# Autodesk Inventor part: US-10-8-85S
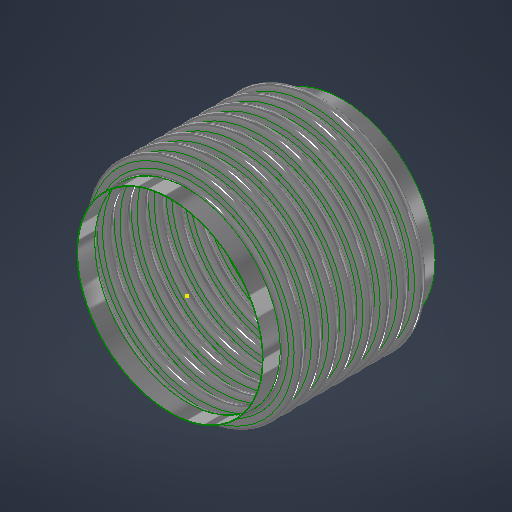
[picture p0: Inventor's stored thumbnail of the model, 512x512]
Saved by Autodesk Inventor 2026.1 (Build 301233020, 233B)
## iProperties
Category: 20 GA (0.036 THICK)
RuleStatus: InUse
Created: 2026-07
Part Number: US-10-8-85S
Project: =STOCK BELLOWS: <Stock Number><SFILL>
Material: ASTM A240-304
Description: =STOCK BELLOWS: <Stock Number>, <SID_> I.D., <SOD_> O.D., <SPLY_> PLY, <Category>, <SNET_CONS> CONS.<PITCH_><STANGENT_> TANGENT<SFILL>
Document SubType Name: Sheet Metal
Designer: LC
Stock Number: U.S-10-8-85S
Surface Area: 659.127 cm^2
Volume: 56.61 cm^3
Sheet Metal Rule: Default
Appearance: STAINLESS STEEL
NET_TUBE: 3.428
COUNTER: 1.500
PBAR: 1.214
PSET: 5.356
PLY: 2
CONS: 2
THK: 0.036
ID: 4.500
OD: 5.500
CONS_: 2
TANGENT: 0.500
PITCH: 0.375
BELLOWS_UPSET: 0.000
NET_CONS: 2
S_CONS: 0
Description_Units: 0
ID_M: 114.30 mm
OD_M: 139.70 mm
THK_M: 0.91 mm
ID_U: 4.500 in
OD_U: 5.500 in
THK_U: 0.036 in
TANGENT2: 0.500
d79: 1.000
d82: 1.000
d83: 26.000
d84: 24.000
d80: 2.571
d81: 10
SID: 2.375
SCONS_: 8
SPITCH: 0.250
SBELLOWS_UPSET: 0.000
SNET_CONS: 8
SS_CONS: 0
SCONS: 8
d174: 8
d177: 0.018
d178: 2.375
d179: 3.000
d180: 0.375
d181: 1.000
d182: 0.000
d190: 8
d191: 1
d192: 1
d193: 8
d194: 0
PART_NUMBER: U.S-10-8-85S
PRESSURE: 85
SIZE: 10.00
STANGENT_: 1.000
d214: 8
d217: 0.030
d218: 6.625
d219: 8.125
d220: 0.500
d221: 1.000
d222: 0.000
d230: 8
d231: 1
d232: 1
d233: 8
d234: 0
STANGENT: 4.000
SPLY_: 1
STHK_: 0.036
SID_: 10.750
SOD_: 12.500
SPITCH_: 1.000
STANGENT__: 1.000
SBELLOWS_UPSET_: 0.000
SDIFF_TAN: 1.000
TAN_TO_TAN: 0.750 in
d252: 2
d275: 2
d287: 0.050
d289: 0.500
d290: 0.000
d263: 2
d265: 1
d268: 2
d269: 0
d286: 2
d288: 1
d291: 2
d292: 0
SOD_NECK: 10 13/16
CFILL: .
SFILL: .
PITCH_: =, <SPITCH_> PITCH,
SREROLL: 0.750
MATTABLE: 20 GA (0.036 THICK)
MESH: ,
CSECT: 2
Author: LC
Keywords: 20 GA (0.036 THICK)
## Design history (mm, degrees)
sketch "Sketch2"
  geometry: L1 (0, -183.595)-(0, 600.956) reference; L2 (58.979, 0)-(57.15, 0); L3 (60.446, -1.467)-(66.554, -1.467); L4 (60.446, -3.296)-(66.554, -3.296); L5 (66.554, -8.058)-(60.446, -8.058); L6 (66.554, -6.229)-(60.446, -6.229); L7 (58.979, -9.525)-(57.15, -9.525); L8 (60.446, 0)-(60.446, -9.525); L9 (66.554, -4.762)-(69.85, -4.763); L10 (57.15, 0)-(57.15, -9.525); L11 (20.376, 102.841)-(20.376, 101.926); L12 (58.262, 488.877)-(58.262, 349.177); L13 (58.262, 479.352)-(58.262, 339.652); L14 (93.133, -58.817)-(93.133, -71.517); L15 (118.746, -66.401)-(118.746, -66.401); L16 (66.554, -6.229)-(66.554, -8.058); L17 (60.446, -6.229)-(60.446, -8.058); L18 (60.446, -7.144)-(66.554, -7.144); L19 (69.85, 0)-(69.85, -9.525); L20 (-66.554, -6.229)-(-66.554, -8.058); L21 (-66.554, -1.467)-(-60.446, -1.467); L22 (-66.554, -3.296)-(-60.446, -3.296); L23 (-60.446, -6.229)-(-66.554, -6.229); L24 (-66.554, -7.144)-(-60.446, -7.144); L25 (-60.446, -8.058)-(-66.554, -8.058); L26 (-60.446, -6.229)-(-60.446, -8.058); L27 (-57.15, -2.522)-(-57.15, -12.047); L28 (-60.446, -4.763)-(-57.15, -4.763); L29 (-66.554, 3.828)-(-66.554, -9.525); L30 (-68.021, 0)-(-69.85, 0); L31 (-69.85, 0)-(-69.85, -9.525); L32 (-68.021, -9.525)-(-69.85, -9.525); A1 r 1.467 centre (60.446, 0) between (58.979, 0) and (60.446, -1.467); A2 r 3.296 centre (60.446, 0) between (57.15, 0) and (60.446, -3.296); A3 r 3.296 centre (66.554, -4.762) between (66.554, -8.058) and (66.554, -1.467); A4 r 1.467 centre (66.554, -4.762) between (66.554, -6.229) and (66.554, -3.296); A5 r 1.467 centre (60.446, -9.525) between (60.446, -8.058) and (58.979, -9.525); A6 r 3.296 centre (60.446, -9.525) between (60.446, -6.229) and (57.15, -9.525); A7 r 2.381 centre (66.554, -4.762) between (66.554, -7.144) and (68.936, -4.762); A8 r 2.381 centre (60.446, -9.525) between (60.446, -7.144) and (58.064, -9.525); A9 r 1.467 centre (-66.554, -9.525) between (-66.554, -8.058) and (-68.021, -9.525); A10 r 1.467 centre (-60.446, -4.763) between (-60.446, -6.229) and (-60.446, -3.296); A11 r 2.381 centre (-60.446, -4.763) between (-60.446, -7.144) and (-58.064, -4.763); A12 r 3.296 centre (-60.446, -4.763) between (-60.446, -8.058) and (-60.446, -1.467); A13 r 2.381 centre (-66.554, -9.525) between (-66.554, -7.144) and (-68.936, -9.525); A14 r 3.296 centre (-66.554, -9.525) between (-66.554, -6.229) and (-69.85, -9.525); A15 r 1.467 centre (-66.554, 0) between (-68.021, 0) and (-66.554, -1.467); A16 r 3.296 centre (-66.554, 0) between (-69.85, 0) and (-66.554, -3.296); 10 further points
  constraints: 62 end point, 38 point on circle, 20 tangent, 16 centre point, 12 parallel, 9 midpoint, 7 vertical, 6 coincident, 6 concentric, 6 point on line, 4 equal radius, 4 perpendicular, 3 horizontal, 1 collinear, 1 horizontal alignment, 10 other
  dimensions: "THK" = 0.9144 distance of L11.start L11.end; "ID" = 114.3 distance of L11.end point (20.376, -12.374); "OD" = 139.7 distance of L12.start L12.end; "PITCH" = 9.525 distance of L12.start L13.start; "TANGENT" = 12.7 distance of L14.start L14.end; "BELLOWS_UPSET" = 0 distance of L15.start L15.end; "d43" = 114.3 diameter of L10 L1 (= ID); "d44" = 139.7 diameter of L9.end L1 (= OD); "d45" = 1.8288 distance between parallel lines of L5 L6 (computed from THK, PLY); "d46" = 3.29565 radius of A3 (computed from PITCH, THK, PLY); "UPSET_PITCH" = 9.525 distance of L2.end L7.end (derived); "SIDEWALL_ANGLE" = 0 deg angle of L3 L9 (derived); "CON_GAP" = 2.9337 distance of point (60.446, -6.229) point (60.446, -3.296) (derived); "TAN1" = 3.74046 dimension on A8 (derived); "TAN2" = 3.74046 dimension on A7 (derived); "LEG1" = 6.1087 distance of L18.start L18.end (derived); "d278" = 1.8288 distance between parallel lines of L25 L23 (derived); "d279" = 3.29565 radius of A12 (derived); "d280" = 9.525 distance of L30.end L31.end (derived); "d281" = 360 deg dimension on L21 L28 (derived); "d282" = 2.9337 distance of point (-66.554, -6.229) point (-66.554, -3.296) (derived); "d283" = 3.74046 dimension on A13 (derived); "d284" = 3.74046 dimension on A11 (derived); "d285" = 6.1087 distance of L24.start L24.end (derived); "d293" = 114.3 diameter of L27 L1 (derived); "d294" = 139.7 diameter of L31 L1 (derived)
  node "Sketch Rectangular Pattern1" dims "d31" = 25.4, "ID" = 114.3
  node "Sketch Rectangular Pattern2" dims "d39" = 25.4, "PITCH" = 9.525
revolve "CONS" stored, may be unused: angle "d48" = 90 deg
node "BELLOW MIDPLANE"
pattern_linear "Rectangular Pattern2" dims "d52" = 9.525 (= UPSET_PITCH)
sketch "Sketch5"
  geometry: C1 r 58.979 at (0, 0) reference; C2 r 57.15 at (0, 0) reference
extrude "TANGENT" new body sketch "Sketch5" distance "d53" = 12.7 (= TANGENT); taper "d54" = 0 deg
revolve "SAMETAN" stored, may be unused: angle "d65" = 90 deg
revolve "DIFFTAN" stored, may be unused: angle "d70" = 90 deg
sketch "Sketch9"
  geometry: L1 (58.391, 0)-(-58.391, 0) reference; L2 (0, -17.78)-(0, 17.78) reference; L3 (41.708, 0)-(-41.708, 0); L4 (41.708, -11.906)-(41.708, 11.906); L5 (29.008, -11.906)-(29.008, 11.906); L6 (15.418, 11.906)-(15.418, -11.906); L7 (-29.008, -11.906)-(-29.008, 11.906); L8 (-41.708, -11.906)-(-41.708, 11.906); L9 (40.914, -11.906)-(40.914, 11.906); L10 (41.708, -11.906)-(40.914, -11.906); L11 (41.708, 11.906)-(40.914, 11.906); L12 (15.815, 11.906)-(15.022, 11.906); L13 (15.022, 11.906)-(15.022, -11.906); L14 (15.022, -11.906)-(15.815, -11.906); L15 (15.815, -11.906)-(15.815, 11.906); L16 (-15.815, 11.906)-(-15.815, -11.906); L17 (-15.418, 11.906)-(-15.418, -11.906); L18 (-15.815, -11.906)-(-15.022, -11.906); L19 (-15.022, -11.906)-(-15.022, 11.906); L20 (-15.022, 11.906)-(-15.815, 11.906); L21 (-41.708, -11.906)-(-40.914, -11.906); L22 (-40.914, -11.906)-(-40.914, 11.906); L23 (-40.914, 11.906)-(-41.708, 11.906); L24 (-41.708, 11.906)-(-41.708, -11.906); L25 (41.708, -0.397)-(-41.708, -0.397); L26 (-41.708, -0.397)-(-41.708, 0.397); L27 (-41.708, 0.397)-(41.708, 0.397); L28 (41.708, 0.397)-(41.708, -0.397); L29 (-41.708, 11.906)-(41.708, 11.906); L30 (41.708, 11.906)-(41.708, 12.7); L31 (41.708, 12.7)-(-41.708, 12.7); L32 (-41.708, 12.7)-(-41.708, 11.906); L33 (41.708, -11.906)-(-41.708, -11.906); L34 (-41.708, -11.906)-(-41.708, -12.7); L35 (-41.708, -12.7)-(41.708, -12.7); L36 (41.708, -12.7)-(41.708, -11.906); 30 further points
  constraints: 68 end point, 13 midpoint, 13 parallel, 8 horizontal, 7 perpendicular, 6 equal length, 3 point on line, 2 vertical, 14 other
  dimensions: "d115" = 23.8125 distance of L4.start L4.end (derived); "d116" = 12.7 distance between parallel lines of L4 L5 (derived); "d117" = 13.58962 distance between parallel lines of L5 L6 (derived); "d125" = 44.42645 distance between parallel lines of L7 L6 (derived); "d127" = 12.7 distance between parallel lines of L8 L7 (derived); "d128" = 26.28962 distance between parallel lines of L6 L4 (derived); "d130" = 83.41607 distance between parallel lines of L8 L4 (derived); "RULER_THK" = 0.79375 distance between parallel lines of L4 L9; "d135" = 0.79375 distance of L13.end L14.end (derived); "d138" = 30.83684 distance of L13.end L16.end (derived); "d143" = 0.79375 distance of L22.end L8.end (derived); "d144" = 0.79375 distance between parallel lines of L27 L25 (derived)
extrude "RULER" join sketch "Sketch9" distance "d149" = 0.79375 (derived); taper "d150" = 0 deg
extrude "BARS" join sketch "Sketch9" distance "d151" = 0.79375 (derived); taper "d152" = 0 deg
pattern_linear "Rectangular Pattern4" dims "d155" = 30.83684 (derived)
sketch "Sketch13"
  geometry: L1 (93.149, -52.467)-(93.149, -77.867); L2 (137.439, 0)-(136.525, 0); L3 (137.439, -25.4)-(136.525, -25.4); L4 (151.943, -19.507)-(143.332, -19.507); L5 (151.943, -18.593)-(143.332, -18.593); L6 (151.943, -12.7)-(158.75, -12.7); L7 (143.332, -5.893)-(151.943, -5.893); L8 (143.332, 0)-(143.332, -25.4); L9 (136.525, 0)-(136.525, -25.4); L10 (58.254, -287.939)-(58.254, -605.439); L11 (58.254, -313.339)-(58.254, -630.839); L12 (58.254, -364.139)-(58.254, -681.639); L13 (58.254, -389.539)-(58.254, -707.039); L14 (58.254, -414.939)-(58.254, -732.439); L15 (58.254, -440.339)-(58.254, -757.839); L16 (58.254, -465.739)-(58.254, -783.239); L17 (58.254, -338.739)-(58.254, -656.239); L18 (20.376, 102.841)-(20.376, 101.926); L19 (143.332, -6.807)-(151.943, -6.807); L20 (0, -810.565)-(0, 254.897) reference; L21 (-25.718, 0)-(154.305, 0) reference; A1 r 5.893 centre (143.332, 0) between (137.439, 0) and (143.332, -5.893); A2 r 5.893 centre (143.332, -25.4) between (143.332, -19.507) and (137.439, -25.4); A3 r 6.807 centre (143.332, -25.4) between (143.332, -18.593) and (136.525, -25.4); A4 r 5.893 centre (151.943, -12.7) between (151.943, -18.593) and (151.943, -6.807); A5 r 6.807 centre (151.943, -12.7) between (151.943, -19.507) and (151.943, -5.893); A6 r 6.807 centre (143.332, 0) between (136.525, 0) and (143.332, -6.807); 6 further points; 1 other entity
  constraints: 38 end point, 15 point on circle, 9 tangent, 6 centre point, 6 parallel, 5 vertical alignment, 4 point on line, 4 vertical, 3 coincident, 3 concentric, 2 collinear, 2 equal radius, 1 horizontal, 1 perpendicular, 23 other
  dimensions: "SBELLOWS_UPSET_" = 0 distance of point (118.762, -66.401) point (118.762, -66.401); "STOTAL_THK_BELLOW__" = 0.9144 distance between parallel lines of L4 L5 (derived); "d224" = 6.8072 radius of A5 (derived); "d225" = 25.4 distance of L2.end L3.end (derived); "SSIDEWALL_ANGLE_" = 0 deg angle of L7 L6 (derived); "SSCON_GAP_" = 11.7856 distance of point (143.332, -18.593) point (143.332, -6.807) (derived); "d235" = 273.05 diameter of L9 L20 (derived); "d236" = 317.5 diameter of L6.end L20 (derived)
  node "Sketch Rectangular Pattern4" dims "d228" = 25.4
  node "Sketch Rectangular Pattern5" dims "d229" = 25.4
revolve "SBELLOW" stored, may be unused: angle "d197" = 90 deg
pattern_linear "Rectangular Pattern5" dims "d204" = 25.4 (derived)
revolve "STANGENT" stored, may be unused: angle "d240" = 90 deg
revolve "SSAMETAN" stored, may be unused: angle "d241" = 90 deg
revolve "SDIFFTAN" stored, may be unused: angle "d246" = 90 deg
revolve "INVCON" stored, may be unused: angle "d295" = 90 deg
pattern_linear "Rectangular Pattern6" dims "d298" = 9.525 (derived)
revolve "INVTANGENT" stored, may be unused: angle "d302" = 90 deg
revolve "INVSAMETAN" stored, may be unused: angle "d307" = 90 deg
revolve "INVDIFFTAN" stored, may be unused: angle "d312" = 90 deg
sketch "ID BELLOW MOUNT CALC"
  geometry: L1 (44.45, 0)-(38.1, 0); L2 (38.1, 0)-(38.1, 12.7); L3 (38.1, 12.7)-(44.45, 12.7); L4 (44.45, 12.7)-(44.45, 0); L5 (36.513, 12.7)-(34.684, 12.7); L6 (34.684, 12.7)-(34.684, 0); L7 (34.684, 0)-(36.513, 0); L8 (36.513, 0)-(36.513, 12.7); L9 (0, -2.54)-(0, 15.24) reference; L10 (-8.89, 0)-(53.34, 0) reference; 1 further point
  constraints: 16 end point, 5 parallel, 2 collinear, 2 horizontal, 2 perpendicular
  dimensions: "d314" = 12.7 distance of L5.end L6.end (derived); "d315" = 1.8288 distance of L5.start L5.end (derived); "IG" = 1.5875 distance between parallel lines of L2 L8; "PIPE_OD" = 88.9 diameter of L4 L9; "PIPE_WALL" = 6.35 distance of L2.end L3.end; "ID_MT_BELLOW" = 69.3674 diameter of L6 L9 (derived)
revolve "CFILL" stored, may be unused: angle "d320" = 90 deg
pattern_linear "Rectangular Pattern7" dims "d323" = 9.525 (derived)
revolve "SFILL" stored, may be unused: angle "d324" = 90 deg
pattern_linear "Rectangular Pattern8" dims "d327" = 25.4 (derived)
node "STOCK BELLOW MIDPLANE"
sketch "Sketch21"
  geometry: L1 (0, -222.25)-(0, 222.25) reference; L2 (-222.25, 0)-(222.25, 0) reference; L3 (-0.099, 71.437)-(0.099, 71.437); L4 (0.099, 71.437)-(0.099, 55.562); L5 (0.099, 55.562)-(-0.099, 55.562); L6 (-0.099, 55.562)-(-0.099, 71.437); C1 r 55.562 at (0, 0); C2 r 71.437 at (0, 0); 3 further points
  constraints: 8 end point, 2 centre point, 2 coincident, 2 parallel, 2 tangent, 1 horizontal, 1 perpendicular, 1 other
  dimensions: "d329" = 111.125 diameter of C1 (derived); "d330" = 142.875 diameter of C2 (derived); "d331" = 0.19844 distance of L3.start L3.end
extrude "CLAMSHELL" cut sketch "Sketch21" extent not by distance; stored distance "d332" = 0; taper "d333" = 0 deg
pattern_circular "Circular Pattern1" dims angle "d335" = 180 deg (derived)
node "BELLOW"
sketch "Sketch6"
  geometry: L1 (-19.05, 58.979)-(-6.35, 58.979); L2 (-6.35, 58.979)-(-6.35, 57.15); L3 (-6.35, 57.15)-(-19.05, 57.15); L4 (-19.05, 57.15)-(-19.05, 58.979); L5 (2.54, 0)-(-59.69, 0) reference; L6 (-38.1, -108.388)-(-38.1, 156.601) reference; 1 further point
  constraints: 8 end point, 2 parallel, 1 horizontal, 1 perpendicular
  dimensions: "d61" = 12.7 distance of L2.end L3.end (derived); "d62" = 1.8288 distance of L1.end L2.end (derived); "d63" = 114.3 diameter of L3 L5 (derived); "d64" = 19.05 distance between parallel lines of L4 L6 (derived)
sketch "Sketch12"
  geometry: 1 further point
sketch "Sketch14"
  geometry: L1 (-25.4, 137.439)-(0, 137.439); L2 (0, 137.439)-(0, 136.525); L3 (0, 136.525)-(-25.4, 136.525); L4 (-25.4, 136.525)-(-25.4, 137.439); L5 (5.08, 0)-(-30.48, 0) reference; L6 (0, -22.06)-(0, 132.359) reference; 1 further point
  constraints: 8 end point, 2 parallel, 1 collinear, 1 horizontal, 1 perpendicular
  dimensions: "d237" = 0.9144 distance of L3.end L1.start (derived); "d238" = 273.05 diameter of L3 L5 (derived); "d239" = 25.4 distance of L1.start L1.end (derived); "SOD_NECK" = 274.8788 diameter of L1 L5 (derived)
sketch "Sketch15"
  geometry: L1 (-22.06, 0)-(132.359, 0) reference; L2 (136.525, -203.2)-(137.439, -203.2); L3 (137.439, -203.2)-(137.439, -228.6); L4 (137.439, -228.6)-(136.525, -228.6); L5 (136.525, -228.6)-(136.525, -203.2); L6 (0, -154.94)-(0, 40.64) reference; 1 further point
  constraints: 8 end point, 2 parallel, 1 horizontal, 1 perpendicular
  dimensions: "d205" = 25.4 distance of L4.end L2.start (derived); "d206" = 0.9144 distance of L3.end L4.end (derived); "d207" = 273.05 diameter of L5 L6 (derived); "d208" = 203.2 distance between parallel lines of L1 L2 (derived)
node "TANGENT_"
node "SAME_TAN"
sketch "Sketch8"
  geometry: L1 (58.979, -19.05)-(57.15, -19.05); L2 (57.15, -19.05)-(57.15, -31.75); L3 (57.15, -31.75)-(58.979, -31.75); L4 (58.979, -31.75)-(58.979, -19.05); L5 (0, -40.64)-(0, 21.59) reference; L6 (-108.388, 0)-(156.601, 0) reference; 1 further point
  constraints: 8 end point, 2 parallel, 1 horizontal, 1 perpendicular
  dimensions: "d66" = 114.3 diameter of L2 L5 (derived); "TOTAL_THK_BELLOW" = 1.8288 distance of L2.end L3.end (derived); "d68" = 19.05 distance between parallel lines of L1 L6 (derived); "d69" = 12.7 distance of L1.end L2.end (derived)
node "DIFF_TAN"
node "Sketch Rectangular Pattern3" dims "d138" = 30.83684 (derived), "d141" = 25.4
node "SBELLOW_"
node "STANGENT_"
node "SSAME_TAN"
sketch "Sketch16"
  geometry: L1 (137.439, -203.2)-(136.525, -203.2); L2 (136.525, -203.2)-(136.525, -228.6); L3 (136.525, -228.6)-(137.439, -228.6); L4 (137.439, -228.6)-(137.439, -203.2); L5 (0, -154.94)-(0, 40.64) reference; L6 (-22.06, 0)-(132.359, 0) reference; 1 further point
  constraints: 8 end point, 2 parallel, 1 horizontal, 1 perpendicular
  dimensions: "SDIFF_TAN" = 25.4 distance of L3.end L1.start; "d243" = 0.9144 distance of L2.end L3.end (derived); "d244" = 203.2 distance between parallel lines of L1 L6 (derived); "d245" = 273.05 diameter of L2 L5 (derived)
node "SDIFF_TAN"
body "Solid15"
sketch "Sketch17"
  geometry: L1 (69.85, 12.7)-(68.021, 12.7); L2 (68.021, 12.7)-(68.021, 0); L3 (68.021, 0)-(69.85, 0); L4 (69.85, 0)-(69.85, 12.7); L5 (0, -2.54)-(0, 15.24) reference; L6 (-13.97, 0)-(83.82, 0) reference; 2 further points
  constraints: 8 end point, 2 parallel, 1 horizontal, 1 midpoint, 1 perpendicular, 1 point on line
  dimensions: "INVTANGENT" = 12.7 distance of L3.end L1.start (derived); "d300" = 1.8288 distance of L1.start L1.end (derived); "d301" = 139.7 diameter of L4 L5 (derived)
body "Solid16"
sketch "Sketch18"
  geometry: L1 (69.85, -19.05)-(68.021, -19.05); L2 (68.021, -19.05)-(68.021, -31.75); L3 (68.021, -31.75)-(69.85, -31.75); L4 (69.85, -31.75)-(69.85, -19.05); L5 (-13.97, 0)-(83.82, 0) reference; L6 (0, -40.64)-(0, 21.59) reference; 1 further point
  constraints: 8 end point, 2 parallel, 1 horizontal, 1 perpendicular
  dimensions: "d303" = 19.05 distance between parallel lines of L1 L5 (derived); "d304" = 12.7 distance of L3.end L1.start (derived); "d305" = 1.8288 distance of L2.end L3.end (derived); "d306" = 139.7 diameter of L4 L6 (derived)
body "Solid17"
sketch "Sketch19"
  geometry: L1 (69.85, -19.05)-(68.021, -19.05); L2 (68.021, -19.05)-(68.021, -31.75); L3 (68.021, -31.75)-(69.85, -31.75); L4 (69.85, -31.75)-(69.85, -19.05); L5 (0, -40.64)-(0, 21.59) reference; L6 (-13.97, 0)-(83.82, 0) reference; 1 further point
  constraints: 8 end point, 2 parallel, 1 horizontal, 1 perpendicular
  dimensions: "d308" = 12.7 distance of L1.end L2.end (derived); "d309" = 139.7 diameter of L4 L5 (derived); "d310" = 1.8288 distance of L2.end L3.end (derived); "d311" = 19.05 distance between parallel lines of L1 L6 (derived)
body "Solid18"
body "Solid19"
body "Solid20"
other parameters: "BMPL" = -101.6, "PSET" = 136.0424 (computed from OD, THK, PLY) [user parameter], "PBAR" = 30.83684 (= 0.570796 x PITCH + OD - ID) [user parameter; used in 1 equation term], "COUNTER" = 15 [user parameter], "NET_TUBE" = 87.07367 (computed from CONS_, PBAR, TANGENT) [user parameter], "S_CONS" = 0 [user parameter; used in 1 equation term], "ID_M" = 114.3 (= ID) [user parameter], "OD_M" = 139.7 (= OD) [user parameter], "THK_M" = 0.9144 (= THK) [user parameter], "ID_U" = 114.3 (= ID) [user parameter], "OD_U" = 139.7 (= OD) [user parameter], "THK_U" = 0.9144 (= THK) [user parameter], "D_UNITS" = 0 [user parameter], "TANGENT2" = 12.7 [user parameter], "TAN_TO_TAN" = 19.05 [user parameter], "OD_NECK" = 117.9576 [user parameter], "d79" = 25.4, "d80" = 65.29823 [user parameter], "d82" = 25.4, "d83" = 660.4, "d84" = 609.6, "sa_0" = 4, "FRAME_THK" = 0.79375 [user parameter], "CON_FLAT" = 13.58962 [user parameter], "SID" = 60.325 [user parameter], "SPITCH" = 6.35 [user parameter], "STANGENT_" = 25.4 [user parameter], "SBELLOWS_UPSET" = 0 [user parameter], "SS_CONS" = 0 [user parameter], "STAN_TO_TAN_" = 203.2 [user parameter], "d100" = 0.9144 [user parameter], "d191" = 25.4 [user parameter], "d194" = 0 [user parameter], "STANGENT" = 101.6 [user parameter], "d234" = 0 [user parameter], "SUPSET_PITCH_" = 25.4 [user parameter], "d269" = 0 [user parameter], "d287" = 1.27, "d289" = 12.7, "d290" = 0, "d292" = 0 [user parameter], "Thickness" = 3.048 (derived), "KFactor" = 4.4, "BendRadius" = 3.048 (derived), "BendReliefWidth" = 3.048 (derived), "BendReliefDepth" = 1.524 (derived), "CornerReliefSize" = 12.192 (derived), "SeamGap" = 0.00508, "MinimumRemnant" = 6.096 (derived), "TransitionRadius" = 3.048 (derived), "JacobiRadiusSize" = 3.048 (derived), "GapSize" = 3.048 (derived), "SREROLL" = 19.05 [user parameter], "CUR_STK_PITCH" = 25.4 [user parameter], "d328" = -101.6 (derived), "CSECTDEG" = 180 deg [user parameter]
